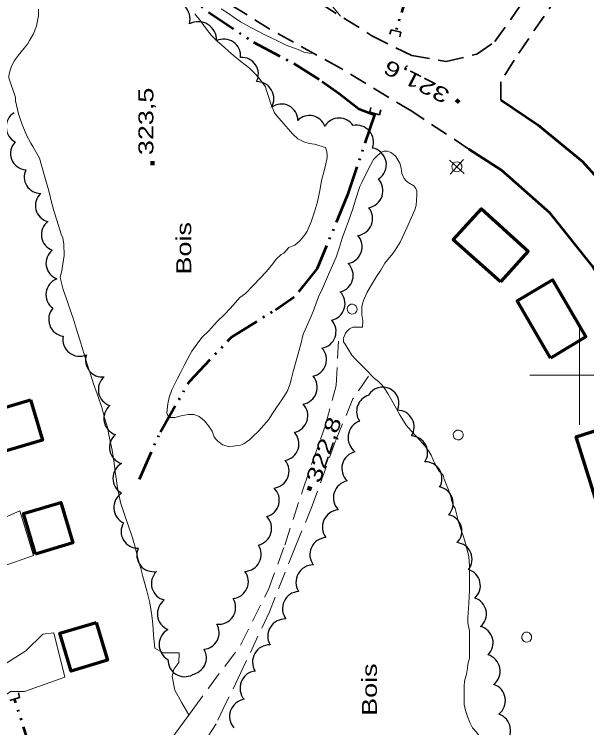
# Model space of a CAD drawing. Extents: x 240591 to 242335, y 5323482 to 5326937.
# Drawn here: x 241286.5 to 241401.5, y 5324929.1 to 5325072.5 of the extents above; entities that cross this region are included whole.
import ezdxf

# ---------------------------------------------------------------- set-up
doc = ezdxf.new("R2010")
doc.units = 0
doc.header["$LTSCALE"] = 1.2
for name, pattern in [('DASH_DOUBLE_DOT', [9.2, 5, -1.2, 0.3, -1.2, 0.3, -1.2]), ('LONG_DASHED', [7.5, 6, -1.5]), ('MEDIUM_DASHED', [4.5, 3, -1.5])]:
    doc.linetypes.add(name, pattern=pattern)
for name, color, linetype, lineweight in [('19', 7, 'Continuous', 13), ('2', 7, 'Continuous', 13), ('21', 7, 'Continuous', 53), ('26', 7, 'Continuous', 35), ('3', 7, 'Continuous', 140), ('31', 7, 'Continuous', 70), ('36', 7, 'Continuous', 13), ('4', 7, 'DASH_DOUBLE_DOT', 53), ('44', 7, 'Continuous', 25), ('61', 7, 'Continuous', 13)]:
    doc.layers.add(name, color=color, linetype=linetype, lineweight=lineweight)

msp = doc.modelspace()

# ---------------------------------------------------------------- linework, layer by layer
at = {"layer": '19', "linetype": 'MEDIUM_DASHED'}
for points in [[(241340.8, 5324965.8), (241344.4, 5324976.9), (241348.9, 5324989.7), (241351.1, 5324997.9), (241351.6, 5325006.8)], [(241357.6, 5324999.8), (241354.5, 5324995.2), (241351, 5324986.8), (241346.3, 5324973.7), (241342.9, 5324965.4)], [(241322.2, 5324932.6), (241325.5, 5324937.1), (241331.9, 5324945.7), (241337.5, 5324956.9), (241340.8, 5324965.8)], [(241342.9, 5324965.4), (241337.7, 5324952.4), (241332, 5324940.2), (241328.9, 5324933.9), (241327, 5324929.9)]]:
    msp.add_lwpolyline(points, dxfattribs=at)
at = {"layer": '19'}
for points in [[(241274.7, 5324964.7), (241276, 5324965.3), (241279.4, 5324966.9), (241284.1, 5324971.2), (241287.6, 5324972.7), (241290.3, 5324963.7), (241284.2, 5324961.6), (241280.2, 5324959.5), (241276.8, 5324957.8)], [(241281.2, 5324942.4), (241284.2, 5324941.7), (241288.8, 5324944.6), (241292.2, 5324947.9), (241294.4, 5324948.2), (241296.6, 5324939.3), (241288.5, 5324936.4), (241285.7, 5324936.4), (241283.4, 5324934.8)], [(241289.7, 5324911.2), (241293.7, 5324909.8), (241298.3, 5324911.2), (241306.8, 5324915.7), (241313.6, 5324920.9), (241319.8, 5324929.3), (241322.2, 5324932.6)], [(241327, 5324929.9), (241322.3, 5324922.7), (241316.3, 5324916.5), (241309.1, 5324912.1), (241300.7, 5324906.5), (241303.4, 5324901.9), (241305.6, 5324896.4), (241305.6, 5324892.7), (241303.1, 5324891.2), (241298.1, 5324891.4), (241293.9, 5324889.5)]]:
    msp.add_lwpolyline(points, dxfattribs=at)
at = {"layer": '2'}
for points in [[(241350.1, 5325074.4), (241352, 5325072.1)], [(241291.3, 5325073.5), (241291.3, 5325072.2), (241291.2, 5325071.6), (241290.9, 5325070.1), (241290.6, 5325069.3), (241290.3, 5325068.6), (241289.5, 5325067.2), (241289.1, 5325066.5), (241288.1, 5325065.3), (241287.3, 5325064.3), (241286.5, 5325063.2), (241285.9, 5325062.1), (241285.6, 5325061.1), (241285.4, 5325060.1), (241285.4, 5325059.7), (241286.7, 5325055.8)], [(241322.7, 5325072.6), (241323.9, 5325071.2), (241324.9, 5325069.8), (241326, 5325068.3), (241327.3, 5325067), (241328, 5325066.4), (241330, 5325064.6), (241332, 5325063), (241333.7, 5325061.7), (241334.7, 5325060.7), (241335.6, 5325059.7)], [(241346.6, 5325064.6), (241345.7, 5325064.7), (241344.6, 5325064.9), (241343.8, 5325065.3), (241341.1, 5325066.3), (241339.2, 5325067.2), (241336.8, 5325068.4), (241335.4, 5325069.1), (241334.1, 5325069.8), (241331.9, 5325071), (241330.4, 5325072), (241329.7, 5325072.5), (241328, 5325073.6)], [(241335.6, 5325059.7), (241336.9, 5325057.9), (241337.1, 5325057.2), (241337.6, 5325055.8), (241338, 5325054.5), (241338.7, 5325052.7), (241339.2, 5325052.1), (241340.1, 5325051.1), (241341, 5325050), (241342.4, 5325048.4), (241343.4, 5325047.5), (241344.6, 5325046.9), (241345.7, 5325046.5), (241346.8, 5325046.4), (241349, 5325045.7), (241349.2, 5325045.1), (241349.3, 5325044.4), (241349.3, 5325043.7), (241349, 5325042.1), (241348.6, 5325040.6), (241348.2, 5325039.1), (241347.9, 5325037.4), (241347.4, 5325034.8), (241346.8, 5325032.8), (241346.1, 5325030.8), (241345.3, 5325028.9), (241344.8, 5325028.2), (241343.8, 5325027), (241342.8, 5325026.1), (241342.3, 5325025.9), (241341.6, 5325025.6)], [(241321.5, 5324931.7), (241320.1, 5324934.1), (241318.7, 5324936.7), (241318.2, 5324939.4), (241318.5, 5324940.9), (241319.5, 5324942.2), (241319.6, 5324944.2), (241317.7, 5324944.2), (241316.4, 5324944.2), (241314.7, 5324945.1), (241314.4, 5324947.7), (241314.3, 5324949.9), (241314.1, 5324951.7), (241313.7, 5324954.2), (241313.1, 5324956.6), (241312.3, 5324959.5), (241311.9, 5324961.1), (241311.4, 5324962.7), (241310.6, 5324965.9), (241310.2, 5324967.3), (241309.3, 5324970), (241308.9, 5324971.2), (241307.8, 5324974.4), (241307.4, 5324976.4), (241307.2, 5324977.3), (241306.7, 5324980.6), (241306.5, 5324982.3), (241306.1, 5324984.9), (241305.6, 5324987.3), (241305.1, 5324989.7), (241304.6, 5324991.4), (241304.1, 5324993.3), (241303.1, 5324996.2), (241302.4, 5324998.2), (241301.8, 5325000.2), (241301.1, 5325002.2), (241300.4, 5325004.4), (241299.8, 5325006.4), (241298.9, 5325009.4), (241298.3, 5325011.4), (241297.7, 5325013.1), (241297, 5325015.1), (241296.3, 5325017.2), (241295.7, 5325019.6), (241296, 5325021), (241296.5, 5325024), (241296.4, 5325026.3), (241296.2, 5325027.6), (241295.9, 5325028.3), (241295, 5325031.1), (241294.5, 5325032.8), (241294, 5325034.5), (241293.4, 5325037), (241292.7, 5325039.3), (241292, 5325041.9), (241291.5, 5325043.6), (241290.2, 5325045.9), (241289.8, 5325046.6), (241288.9, 5325048.2), (241287.9, 5325050.7), (241287.3, 5325052.5), (241286.7, 5325055.1), (241286.7, 5325055.8)], [(241341.6, 5325025.6), (241340.6, 5325024.5), (241340.1, 5325024.2), (241339.1, 5325023.3), (241338.3, 5325022.3), (241337.1, 5325020.8), (241335.8, 5325019.4), (241334.6, 5325018.1), (241332.9, 5325016.4), (241331.8, 5325015.6), (241330.9, 5325014.6), (241329.8, 5325013.4), (241328.6, 5325012.1), (241327.3, 5325010.8), (241325.5, 5325008.8), (241324.2, 5325007.6), (241323.1, 5325006.2), (241322.1, 5325004.8), (241321.3, 5325003.3), (241320.6, 5325001.9), (241319.9, 5325000.6), (241319.2, 5324999.2), (241318.1, 5324997), (241317.6, 5324995.5), (241317.3, 5324994.2), (241317.1, 5324992.4), (241317.4, 5324991.7), (241317.8, 5324991.5), (241318.7, 5324991.5), (241320, 5324991.8), (241321.4, 5324992.1), (241322.5, 5324992.1), (241323.1, 5324991.9), (241323.6, 5324991.7), (241324.7, 5324990.8), (241325.5, 5324989.8), (241326.2, 5324988.7), (241326.6, 5324987.6), (241326.9, 5324987.2), (241327.3, 5324986.8), (241328.3, 5324986), (241329, 5324985.8), (241329.7, 5324985.6), (241330.4, 5324985.7), (241331.9, 5324985.9), (241332.6, 5324986.2), (241333.7, 5324987), (241334.3, 5324987.6), (241335.6, 5324988.8), (241336.6, 5324989.9), (241337.5, 5324991), (241338.3, 5324992.3), (241339.3, 5324993.7), (241340.2, 5324995), (241341.3, 5324996.7), (241341.9, 5324998.2), (241342.1, 5324999.1), (241342.5, 5325000.7), (241343.2, 5325003.3), (241344, 5325006.2), (241344.5, 5325008.2), (241344.9, 5325009.1), (241345.7, 5325010.9), (241346.5, 5325012.8), (241347.6, 5325015.7), (241348.4, 5325017.4), (241349.6, 5325020.2), (241350.4, 5325022), (241351.1, 5325023.7), (241351.7, 5325025.5), (241352.3, 5325027.5), (241353, 5325029.3), (241353.6, 5325030.9), (241354.5, 5325033.4), (241355, 5325035.2), (241355.9, 5325037.9), (241356.3, 5325038.7), (241357.5, 5325041.2), (241358.6, 5325043.3), (241359.4, 5325044.1), (241360.2, 5325044.8), (241360.7, 5325045), (241361.4, 5325045), (241362.1, 5325044.7), (241362.6, 5325044.4), (241363.1, 5325043.9), (241363.9, 5325042.6), (241364.2, 5325041.6), (241364.3, 5325040.5), (241364.8, 5325039.5), (241365.1, 5325039.1), (241365.6, 5325038.7), (241366.7, 5325038), (241367.1, 5325037.5), (241367.3, 5325037), (241367.3, 5325036.2), (241367.2, 5325034.1), (241366.9, 5325033.2), (241366.2, 5325031.5), (241365.3, 5325029.6), (241364, 5325026.7)], [(241364, 5325026.7), (241363, 5325025.1), (241362.5, 5325024.4), (241360.9, 5325022.5), (241360.1, 5325021.1), (241359.2, 5325019.8), (241358, 5325017.8), (241357.3, 5325016.5), (241356.6, 5325015), (241356.4, 5325014.3), (241356.3, 5325013.7), (241356.3, 5325012.1), (241356.5, 5325010.9), (241356.4, 5325009.6), (241355.7, 5325009.6), (241354.5, 5325009.6), (241353.8, 5325009.3), (241353.3, 5325008.8), (241353, 5325008.4), (241352.6, 5325007.4), (241352.6, 5325006.7), (241352.9, 5325006.2), (241353.5, 5325005.2), (241354.3, 5325004), (241355.1, 5325003.1), (241356.9, 5325001.3), (241358.8, 5324999.3), (241359.6, 5324998.7), (241360.3, 5324998), (241360.9, 5324997.2), (241361.5, 5324996.3), (241362.6, 5324994.4), (241364, 5324991.9), (241365.2, 5324989.9), (241366.2, 5324988.8), (241367.1, 5324987.8), (241367.9, 5324986.9), (241368.9, 5324985.8), (241369.8, 5324984.6), (241370.2, 5324983.9), (241370.9, 5324982.3), (241371.8, 5324980.7), (241372.6, 5324979.9), (241372.8, 5324979.1), (241373.1, 5324978.4), (241373.7, 5324976.9), (241374.2, 5324975.3), (241374.3, 5324974.8)], [(241377.9, 5324948.6), (241377.6, 5324950.2), (241377.6, 5324951.3), (241377.8, 5324954.1), (241377.9, 5324956.8), (241377.9, 5324958.7), (241377.9, 5324961.6), (241377.8, 5324963.5), (241377.6, 5324964.3), (241377.2, 5324965.7), (241376.8, 5324967.1), (241376, 5324969.4), (241375.7, 5324970.5), (241375, 5324973.2), (241374.7, 5324973.7), (241374.3, 5324974.8)]]:
    msp.add_lwpolyline(points, dxfattribs=at)
at = {"layer": '2', "linetype": 'LONG_DASHED'}
msp.add_lwpolyline([(241377.9, 5324948.6), (241377.9, 5324945.5), (241377.9, 5324943.1), (241377.6, 5324941.9), (241377.5, 5324941.1), (241377.3, 5324939.9), (241376.9, 5324938.5), (241376.8, 5324937.4), (241376.8, 5324936.3), (241376.8, 5324933.8), (241377.1, 5324932.6), (241377.5, 5324931.4), (241378, 5324930.2), (241378.5, 5324929.1), (241379.3, 5324928.2), (241380, 5324927.3), (241381.7, 5324925.3), (241383, 5324923.9), (241383.6, 5324923.4), (241384.6, 5324922.9), (241385.7, 5324922), (241386.3, 5324921.1), (241386.6, 5324920.8)], dxfattribs=at)
at = {"layer": '21', "linetype": 'MEDIUM_DASHED', "lineweight": 35}
for points in [[(241366.3, 5325064.2), (241373.2, 5325063), (241379.4, 5325064.5), (241383, 5325067), (241395.1, 5325084.2), (241406.9, 5325101.7), (241421.3, 5325123.9), (241435, 5325143.3), (241450.8, 5325165.7), (241464.8, 5325185.7), (241482.4, 5325211.2), (241497.9, 5325233.8), (241512.6, 5325254.2), (241527.4, 5325276.3), (241543.1, 5325299.1), (241556.2, 5325318.2), (241571.8, 5325340.9), (241586.5, 5325362.3), (241601.6, 5325383.9), (241616, 5325405.1), (241631.8, 5325428), (241643, 5325443.8)], [(241648.8, 5325441.1), (241635.8, 5325423.4), (241626.3, 5325409.7), (241615.3, 5325394), (241603.3, 5325375.8), (241590.1, 5325356.4), (241574.6, 5325334.4), (241558.7, 5325310.7), (241548.1, 5325293.5), (241534.7, 5325274.5), (241515.5, 5325247.3), (241501.4, 5325226.9), (241486.9, 5325205.4), (241470.6, 5325181.9), (241454.1, 5325158.1), (241439.1, 5325136.5), (241424.2, 5325115.1), (241409.8, 5325096.8), (241395.9, 5325076.6), (241386.9, 5325063.3), (241384.2, 5325058.9), (241384.2, 5325055.3)], [(241377.8, 5325045.4), (241366.3, 5325053), (241352, 5325061.7), (241337.8, 5325069.5), (241324.6, 5325077.8)], [(241348.1, 5325074.6), (241358.3, 5325068.2), (241366.3, 5325064.2)]]:
    msp.add_lwpolyline(points, dxfattribs=at)
at = {"layer": '21'}
for points in [[(241384.2, 5325055.3), (241391.6, 5325050.3), (241400.6, 5325042.9), (241408.9, 5325033.7), (241416.2, 5325023.1), (241421.7, 5325012.5), (241425.1, 5325003.7), (241430.1, 5324988), (241435, 5324971.1), (241439.4, 5324955), (241441.3, 5324944.5)], [(241429.5, 5324943.1), (241427.1, 5324955.3), (241423.5, 5324969), (241415.9, 5324993.5), (241409.6, 5325010.1), (241402.6, 5325021.9), (241394.1, 5325032.5), (241384.3, 5325041.2), (241377.8, 5325045.4)]]:
    msp.add_lwpolyline(points, dxfattribs=at)
at = {"layer": '26'}
for p, q in [((241362.2, 5325069.4), (241361.9, 5325068.5)), ((241362.2, 5325069.4), (241364.1, 5325068.9)), ((241364.1, 5325068.9), (241363.9, 5325068)), ((241357.9, 5325052.8), (241358.1, 5325053.8)), ((241359.8, 5325052.3), (241357.9, 5325052.8)), ((241359.8, 5325052.3), (241360.1, 5325053.3)), ((241287.5, 5324935.2), (241287.3, 5324936.1)), ((241287.5, 5324935.2), (241285.6, 5324934.6))]:
    msp.add_line(p, q, dxfattribs=at)
at = {"layer": '3'}
for p, q in [((241375.8, 5325054.8), (241375.2, 5325055.3)), ((241314.2, 5325042.2), (241314.2, 5325043)), ((241345.6, 5324976.8), (241345.9, 5324977.6))]:
    msp.add_line(p, q, dxfattribs=at)
at = {"layer": '31'}
for points in [[(241384.1, 5325018.7), (241374.6, 5325027.2), (241380.3, 5325033.4), (241389.7, 5325024.9)], [(241394.2, 5325003.4), (241387.5, 5325014.9), (241394.6, 5325019.1), (241401.3, 5325007.7)], [(241289.7, 5324995), (241292.1, 5324986.9), (241284.6, 5324984.7), (241282.2, 5324992.8)], [(241403.2, 5324975.2), (241399.3, 5324987.6), (241407.3, 5324990.1), (241411.3, 5324977.7)], [(241290.7, 5324964), (241288.3, 5324972.2), (241295.8, 5324974.4), (241298.2, 5324966.3)], [(241302.9, 5324950.3), (241305.2, 5324942.7), (241297.9, 5324940.5), (241295.6, 5324948.1)]]:
    msp.add_lwpolyline(points, close=True, dxfattribs=at)
at = {"layer": '36'}
for p, q in [((241376.8, 5325040.5), (241373.9, 5325043.2)), ((241374, 5325040.4), (241376.7, 5325043.3))]:
    msp.add_line(p, q, dxfattribs=at)
for centre, major_axis in [((241375.374, 5325041.837), (-0.261, 0.965)), ((241354.333, 5325013.25), (0.261, -0.965)), ((241375.643, 5324987.95), (0.261, -0.965)), ((241389.393, 5324947.33), (0.261, -0.965))]:
    msp.add_ellipse(centre, major_axis=major_axis, ratio=0.99964, dxfattribs=at)
at = {"layer": '4'}
for p, q in [((241358.9, 5325052.6), (241358.8, 5325052.3)), ((241290.2, 5324923.6), (241286.5, 5324934.9))]:
    msp.add_line(p, q, dxfattribs=at)
for points in [[(241384.7, 5325110.5), (241378.9, 5325102), (241370.3, 5325088.3), (241366, 5325078.6), (241363.1, 5325069.2)], [(241294.4, 5325080.5), (241303.6, 5325081.8), (241311.2, 5325082.6), (241318.4, 5325078.9), (241325.5, 5325072.9), (241334.5, 5325066.9), (241342.6, 5325062.6), (241348.3, 5325059), (241351.7, 5325056.6), (241355.7, 5325053.5), (241358.8, 5325052.3)], [(241358.8, 5325052.3), (241353.4, 5325036.2), (241347.3, 5325021.4), (241342.7, 5325015.7)], [(241311.6, 5324979.1), (241315.8, 5324988.6), (241321.7, 5324998.8), (241330.1, 5325007.6), (241338.9, 5325013.1), (241342.7, 5325015.7)]]:
    msp.add_lwpolyline(points, dxfattribs=at)
at = {"layer": '44'}
for centre, radius, start, end in [((241294.05, 5325034.062), 3.338, 133.08229, 254.8949), ((241295.239, 5325028.221), 3.332, 128.17269, 250.00787), ((241296.149, 5325022.478), 3.32, 128.11356, 249.93438), ((241307.845, 5324991.254), 3.395, 129.84828, 251.71128), ((241342.042, 5324991.815), 3.397, 281.86372, 43.88829), ((241309.007, 5324985.461), 3.4, 130.92206, 252.94454), ((241340.251, 5324986.177), 3.398, 280.84285, 42.89677), ((241366.154, 5324984.408), 3.343, 326.45084, 88.51888), ((241338.221, 5324980.69), 3.427, 277.19254, 38.8491), ((241369.011, 5324979.194), 3.367, 329.41087, 91.21414), ((241336.321, 5324974.843), 3.378, 284.38186, 46.41717), ((241334.723, 5324969.166), 3.423, 282.94493, 44.61133), ((241375.056, 5324962.973), 3.368, 322.00023, 83.62926), ((241332.658, 5324963.948), 3.4, 271.88856, 33.60079), ((241330.076, 5324958.474), 3.401, 275.63171, 37.61695), ((241376.734, 5324957.694), 3.351, 311.39629, 73.06672)]:
    msp.add_arc(centre, radius, start, end, dxfattribs=at)
for centre, major_axis, ratio, start_param, end_param in [((241318.089, 5325071.481), (2.527, 2.673), 0.999763, 5.2166693, 7.3442368), ((241323.414, 5325067.353), (2.236, 2.899), 0.999643, 5.3219222, 7.4429245), ((241328.552, 5325064.148), (2.126, 2.624), 0.999236, 5.2927939, 7.4189082), ((241332.167, 5325060.496), (2.964, 1.507), 0.999662, 5.3358968, 7.4611458), ((241335.191, 5325055.553), (-2.982, 1.669), 0.999995, 3.1163556, 5.243345), ((241340.145, 5325051.21), (-3.003, 1.371), 0.984142, 3.5520343, 5.7936139), ((241288.167, 5325049.852), (2.982, -1.525), 0.999983, 2.5920497, 4.7185203), ((241345.753, 5325048.893), (-3.251, 0.584), 0.98603, 3.6338274, 5.6858283), ((241351.732, 5325048.36), (-3.268, 0.556), 0.987425, 3.883752, 5.8863594), ((241355.215, 5325046.79), (-1.705, 2.956), 0.999234, 3.832879, 5.9694434), ((241288.991, 5325044.538), (0.959, -3.148), 0.999934, 3.6333555, 5.9244434), ((241357.798, 5325042.275), (3.359, -0.563), 0.996021, 5.4388742, 7.8562), ((241291.75, 5325039.802), (1.585, -2.897), 0.999933, 3.7569422, 5.7884911), ((241357.028, 5325037.058), (3.092, -1.611), 0.999833, 5.3751494, 7.5003239), ((241355.013, 5325031.449), (3.199, -1.245), 0.998911, 5.2167099, 7.3437413), ((241352.93, 5325025.782), (3.108, -1.395), 0.999486, 5.3112362, 7.4342759), ((241351.151, 5325020.01), (-0.876, 3.278), 0.999994, 3.1150542, 5.2451381), ((241296.257, 5325016.169), (-3.362, 0.67), 0.99898, 5.2813258, 7.4068872), ((241349.496, 5325014.341), (3.265, -0.968), 0.999314, 5.2205759, 7.3414569), ((241296.802, 5325011.191), (-3.22, -1.197), 0.999062, 5.2164566, 7.3430086), ((241347.692, 5325008.765), (-2.231, 2.569), 0.999983, 2.5941164, 4.7218785), ((241299.586, 5325007.149), (2.608, -2.148), 0.999936, 3.6368114, 5.824499), ((241345.778, 5325003.094), (3.257, -0.998), 0.995551, 5.2131099, 7.3331735), ((241304.155, 5325002.984), (2.037, -2.696), 0.999857, 3.7373094, 5.7417167), ((241306.715, 5324997.07), (0.602, -3.322), 0.999746, 3.6737445, 5.7890584), ((241343.926, 5324997.52), (3.058, -1.48), 0.999677, 5.3298999, 7.4582365), ((241360.443, 5324994.25), (0.646, 3.252), 0.994447, 4.5013324, 7.506214), ((241358.667, 5324992.65), (-1.622, -3.045), 0.999623, 3.9305114, 5.7917214), ((241363.409, 5324989.573), (3.114, 1.284), 0.999579, 5.3198319, 7.4448354), ((241357.059, 5324987.414), (1.333, -3.287), 0.999995, 3.1193774, 5.2435265), ((241355.745, 5324981.225), (-3.366, 0.898), 0.998047, 5.2173845, 7.3403038), ((241309.68, 5324979.238), (-3.41, -0.01), 0.999639, 5.2213654, 7.3426368), ((241354.056, 5324975.338), (-3.277, 1.19), 0.998696, 5.2759648, 7.3954234), ((241309.876, 5324973.384), (-3.416, -0.224), 0.999994, 5.21997, 7.3460008), ((241371.286, 5324974.198), (3.174, 1.045), 0.999994, 5.2149865, 7.3478994), ((241351.847, 5324969.451), (-3.186, 1.432), 0.999866, 5.2228505, 7.3476887), ((241373.026, 5324968.648), (3.278, 0.682), 0.999469, 5.3083011, 7.4371405), ((241311.279, 5324968.562), (-2.644, -2.093), 0.992081, 5.0689605, 7.2271), ((241349.326, 5324963.89), (-3.038, 1.702), 0.9994, 5.3022853, 7.4271992), ((241314.439, 5324963.843), (-1.26, -3.13), 0.99932, 4.6860158, 6.8391179), ((241346.513, 5324958.351), (-2.835, 2.018), 0.999693, 5.3287299, 7.4593377), ((241317.394, 5324958.092), (2.44, -2.362), 0.999995, 3.113896, 5.2454084), ((241343.823, 5324953.041), (0.355, -3.461), 0.999995, 3.1150114, 5.244206), ((241318.614, 5324952.039), (-3.384, -0.419), 0.99991, 5.2210073, 7.3445758), ((241327.557, 5324953.291), (1.663, 2.934), 0.999604, 3.5408025, 5.7903435), ((241377.947, 5324951.983), (3.338, 0.306), 0.999668, 5.3300626, 7.4587473), ((241340.873, 5324947.495), (-2.974, 1.823), 0.999865, 5.2201825, 7.3439676), ((241324.244, 5324948.242), (1.408, 3.072), 0.999604, 3.6713501, 5.6691806), ((241379.303, 5324946.201), (3.27, 0.723), 0.997776, 5.2592485, 7.3872013), ((241319.025, 5324945.852), (-3.475, -0.01), 0.998033, 5.2191643, 7.3382843), ((241321.676, 5324943.163), (1.858, 2.818), 0.999745, 3.8790954, 5.8298377), ((241337.791, 5324942.317), (-3.023, 1.72), 0.998046, 5.2178687, 7.3454504), ((241380.569, 5324940.473), (3.411, 0.688), 0.999995, 5.2169029, 7.3481233), ((241320.695, 5324942.75), (0.824, -3.274), 0.999729, 4.4423304, 6.5112645), ((241335.3, 5324937.059), (-3.136, 1.542), 0.999512, 5.3067138, 7.4323463), ((241381.633, 5324934.552), (3.454, 0.462), 0.997004, 5.2543622, 7.3737581), ((241333.194, 5324931.402), (-3.241, 1.282), 0.997006, 5.2562282, 7.3767978), ((241382.672, 5324928.55), (3.481, 0.082), 0.999833, 5.3719472, 7.497419)]:
    msp.add_ellipse(centre, major_axis=major_axis, ratio=ratio, start_param=start_param, end_param=end_param, dxfattribs=at)
at = {"layer": '61'}
for points in [[(241400, 5325010), (241400, 5325000), (241400, 5324990)], [(241390, 5325000), (241400, 5325000), (241410, 5325000)]]:
    msp.add_lwpolyline(points, dxfattribs=at)

# ---------------------------------------------------------------- texts
at = {"layer": '3'}
for s, height, rotation, width, p in [('321,6', 2.999, 152.996, 1.4, (241374.2, 5325057.1)), ('323,5', 3, 90, 1.35, (241314.4, 5325044.2)), ('322,8', 3, 70.704, 1.35, (241347.8, 5324978.1))]:
    msp.add_text(s, height=height, rotation=rotation, dxfattribs=dict(at, width=width)).set_placement(p)
at = {"layer": '44', "width": 1.35}
for p in [(241322, 5325020.2), (241359.3, 5324931.5)]:
    msp.add_text('Bois', height=3, rotation=90, dxfattribs=at).set_placement(p)

doc.saveas('drawing.dxf')
